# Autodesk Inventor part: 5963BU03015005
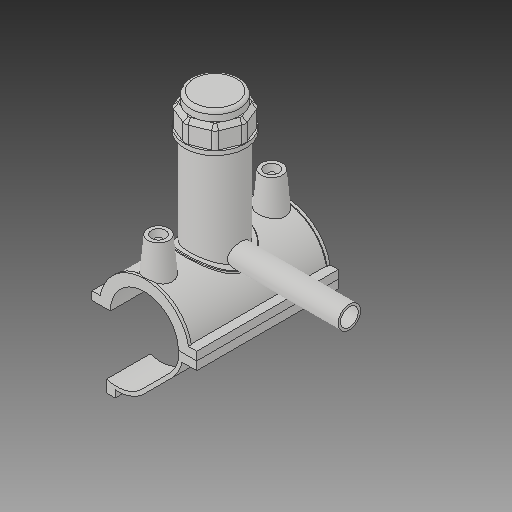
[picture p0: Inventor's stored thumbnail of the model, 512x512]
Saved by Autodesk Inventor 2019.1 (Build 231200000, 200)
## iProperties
Created: 2017-07
Part Number: 5963BU03015005
Material: Generic
Description: PLASSON TAPPING SADDLE 1 1/2''IPS x 1 1/2''CTS
Document SubType Name: Modeling
Designer: KIM
Mass: 1712.7 g
Surface Area: 2671.49 cm^2
Volume: 1712.7 cm^3
Density: 1 g/cm^3
Appearance: Default
Author: KIM
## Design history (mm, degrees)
derived "5963B.ipt"
feature "Solid1::5963B.ipt"
feature "Solid2::5963B.ipt"
feature "Solid4::5963B.ipt"
feature "Solid5::5963B.ipt"
tag "TaggingFeature1"
body "Solid1"
body "Solid2"
other parameters: "d_" = 48.1, "B_" = 74.168, "L_" = 100.076, "d_t" = 6, "H_2" = 98.044, "H_1" = 6.858, "d_1" = 15.8, "H_" = 94.996, "d1" = 62.53, "d148" = 0.7215, "d160" = 0.7215, "d169" = 3.2805, "d192" = 6.1236, "d0" = 48.1, "d2" = 74.168, "d3" = 12.025, "d4" = 100.076, "d5" = 0, "d6" = 0.1, "d8" = 0, "d19" = 6, "d20" = 6, "d21" = 60.0456, "d23" = 0, "d24" = 30.0228, "d26" = 0, "d29" = 3, "d30" = 16.03333, "d31" = 6, "d32" = 0, "d33" = 0, "d34" = 0.6, "d40" = 32.5156, "d41" = 43.29, "d43" = 0, "d45" = 0, "d47" = 91.3106, "d70" = 15, "d72" = 0, "d73" = 6, "d75" = 5, "d76" = 0, "d77" = 2.405, "d78" = 54.05, "d79" = 15, "d80" = 40.0304, "d82" = 5 deg, "d84" = 4, "d85" = 14, "d86" = 0, "d87" = 3, "d88" = 0, "d89" = 1, "d90" = 1, "d91" = 80.0608, "d92" = 0, "d93" = 0.5, "d94" = 25.31579, "d96" = 63.7806, "d97" = 2.00152, "d98" = 0, "d102" = 0.481, "d120" = 140 deg, "d121" = 24.228, "d122" = 20 deg, "d123" = 125.06, "d124" = 37.518, "d126" = 0, "d143" = 49.543, "d145" = 11.1, "d149" = 0.7215, "d150" = 12.21, "d153" = 100.076, "d154" = 0, "d156" = 31.265, "d157" = 160 deg, "d159" = 2.886, "d161" = 0.7215, "d162" = 60.0456, "d163" = 0, "d164" = 24.05, "d167" = 4.81, "d168" = 30.50244, "d170" = 3.2805, "d172" = 0, "d173" = 1, "d175" = 24.05, "d176" = 20 deg, "d177" = 3.367, "d178" = 14.43, "d180" = 0, "d183" = 5.772, "d184" = 2.6936, "d185" = 32.5247, "d186" = 32.5247, "d187" = 31.265, "d188" = 4.329, "d189" = 3.367, "d190" = 0, "d191" = 46.8975, "d193" = 6.1236, "d194" = 3.50266, "d195" = 90 deg, "d197" = 0, "d199" = 0, "d200" = 7.215, "d202" = 0, "d203" = 98.044, "d204" = 41.1255, "d205" = 30.303, "d206" = 36.7965, "d207" = 73.533, "d208" = 76.47432, "d209" = 91.18092, "d210" = 37.2294, "d211" = 43.29, "d212" = 34.632, "d213" = -0.9378, "d216" = 0, "d217" = 4.81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
